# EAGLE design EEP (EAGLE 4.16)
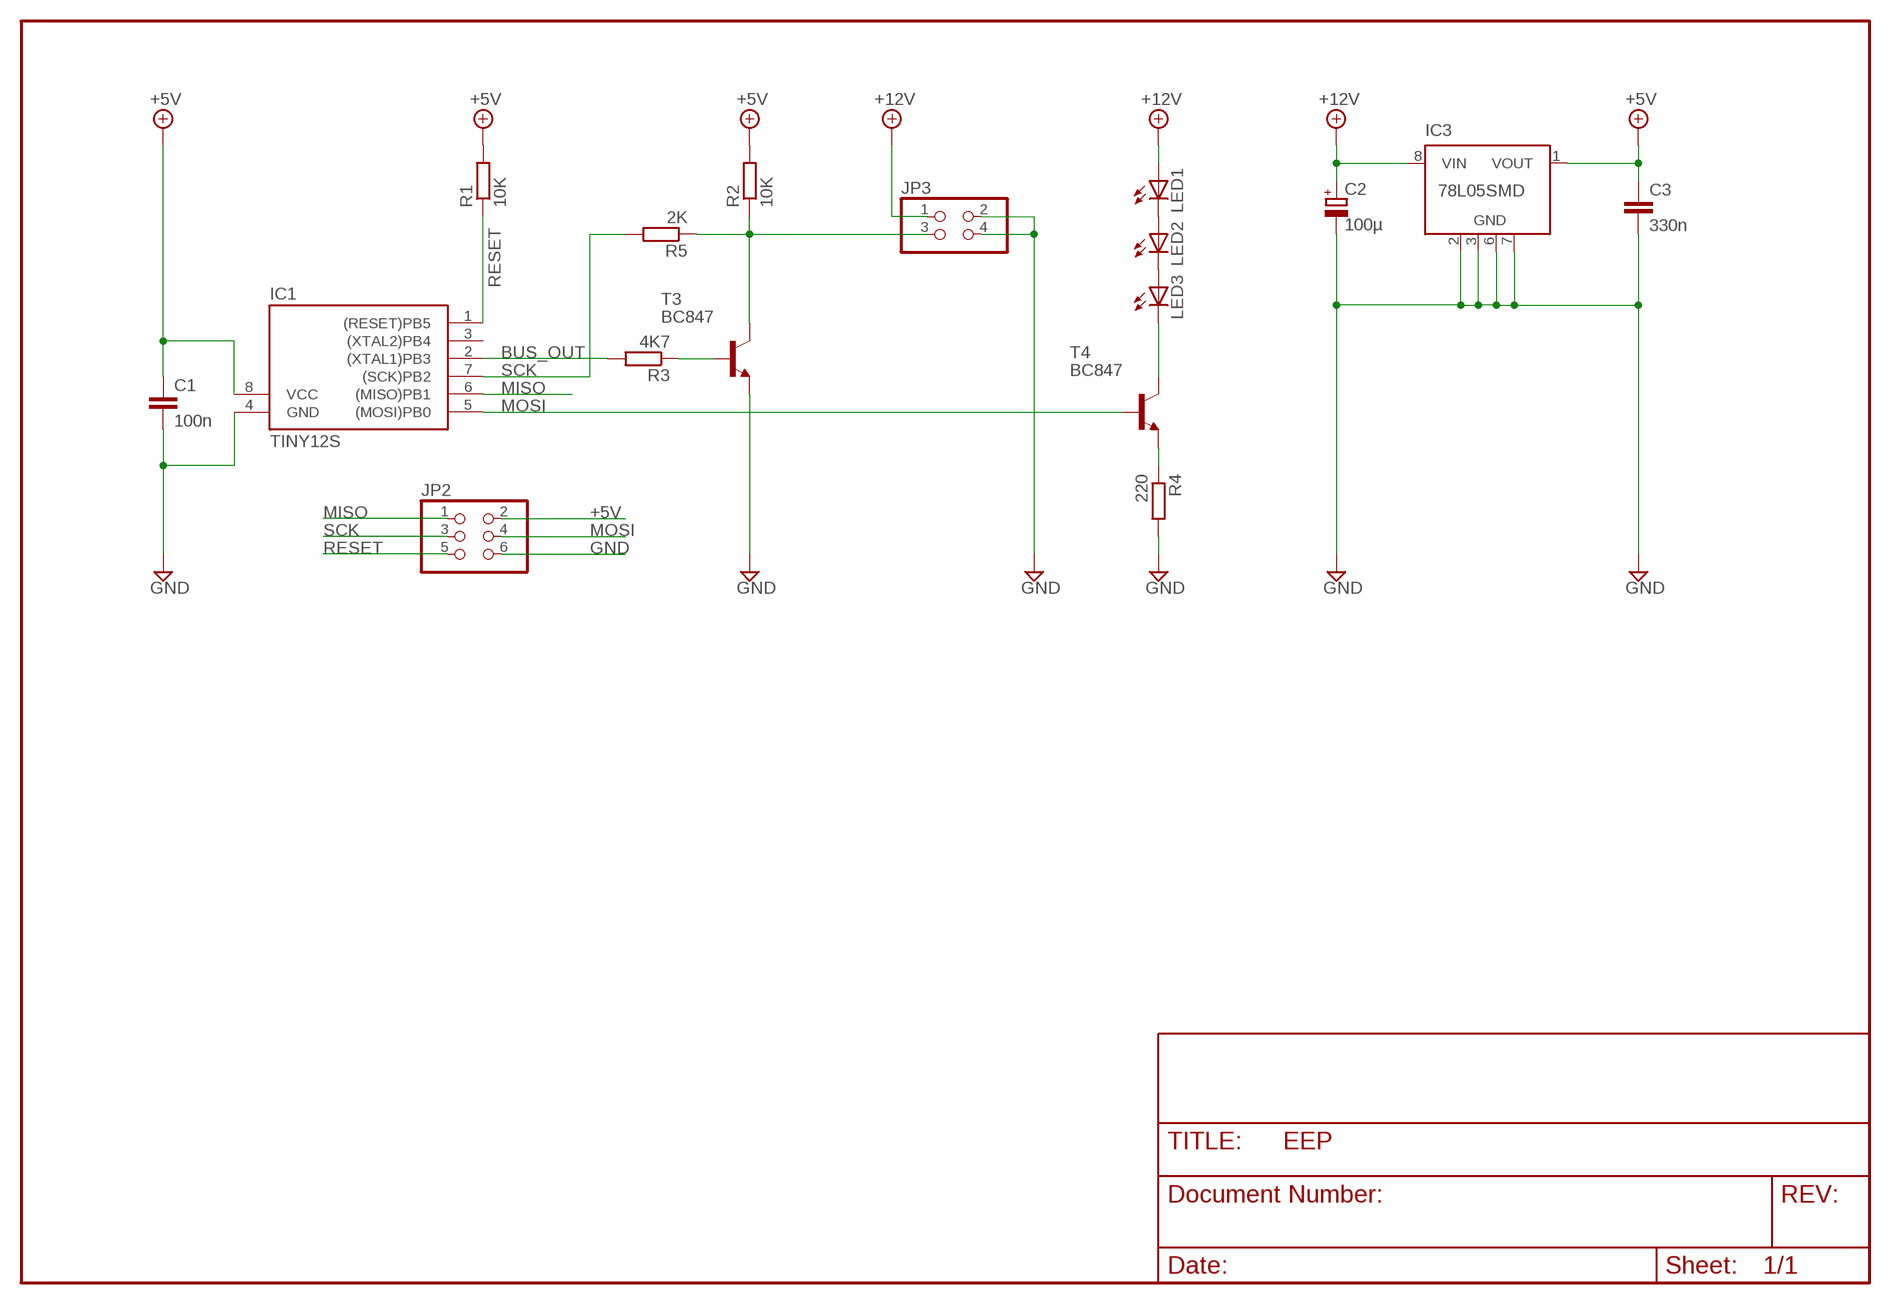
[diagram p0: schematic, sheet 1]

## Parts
C1  100n  C-EUC1206  [C1206]
C2  100µ  CPOL-EU153CLV-0605  [153CLV-0605]
C3  330n  C-EUC1812  [C1812]
IC1  TINY12S  [SOIC8]
IC3  78L05SMD  [SO08]
JP2  PINHD-2X3_2.54-SMD  [2X03SMD]
JP3  PINHD-2X2_2.54-SMD  [2X02SMD]
LED1  LED5MM  [LED5MM]
LED2  LED5MM  [LED5MM]
LED3  LED5MM  [LED5MM]
R1  10K  R-EU_R1206  [R1206]
R2  10K  R-EU_R1206  [R1206]
R3  4K7  R-EU_R1206  [R1206]
R4  220  R-EU_R1206  [R1206]
R5  2K  R-EU_R1206  [R1206]
T3  BC847  [SOT23]
T4  BC847  [SOT23]

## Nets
+5V: C1.1 C3.1 IC1.8(VCC) IC3.1(VOUT) JP2.2 R1.2 R2.2
+12V: C2.+ IC3.8(VIN) JP3.1 LED1.A
BUS_OUT: IC1.2((XTAL1)PB3) R3.2
GND: C1.2 C2.- C3.2 IC1.4(GND) IC3.2(GND) IC3.3(GND) IC3.6(GND) IC3.7(GND) JP2.6 JP3.2 JP3.4 R4.2 T3.2(E)
MISO: IC1.6((MISO)PB1) JP2.1
MOSI: IC1.5((MOSI)PB0) JP2.4 T4.1(B)
N$1: LED3.K(C) T4.3(C)
N$2: R4.1 T4.2(E)
N$3: JP3.3 R2.1 R5.1 T3.3(C)
N$5: R3.1 T3.1(B)
N$6: LED2.K(C) LED3.A
N$7: LED1.K(C) LED2.A
RESET: IC1.1((RESET)PB5) JP2.5 R1.1
SCK: IC1.7((SCK)PB2) JP2.3 R5.2
Unconnected: IC1.3((XTAL2)PB4) IC3.4(NC) IC3.5(NC)

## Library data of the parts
C1 C3 = rcl:C-EU: CAPACITOR, European symbol
C2 = rcl:CPOL-EU: POLARIZED CAPACITOR, European symbol
IC1 = avr-1:TINY12*: MICROCONTROLLER 1 Kbytes FLASH 64 bytes EEPROM
IC3 = linear:78L*SMD: Positive VOLTAGE REGULATOR
JP2 = pinhead-1:PINHD-2X3: PIN HEADER
JP3 = pinhead-1:PINHD-2X2: PIN HEADER
LED1-LED3 = led:LED: LED
R1-R5 = rcl:R-EU_: RESISTOR, European symbol
T3 T4 = transistor:BC847: NPN TRANSISTOR

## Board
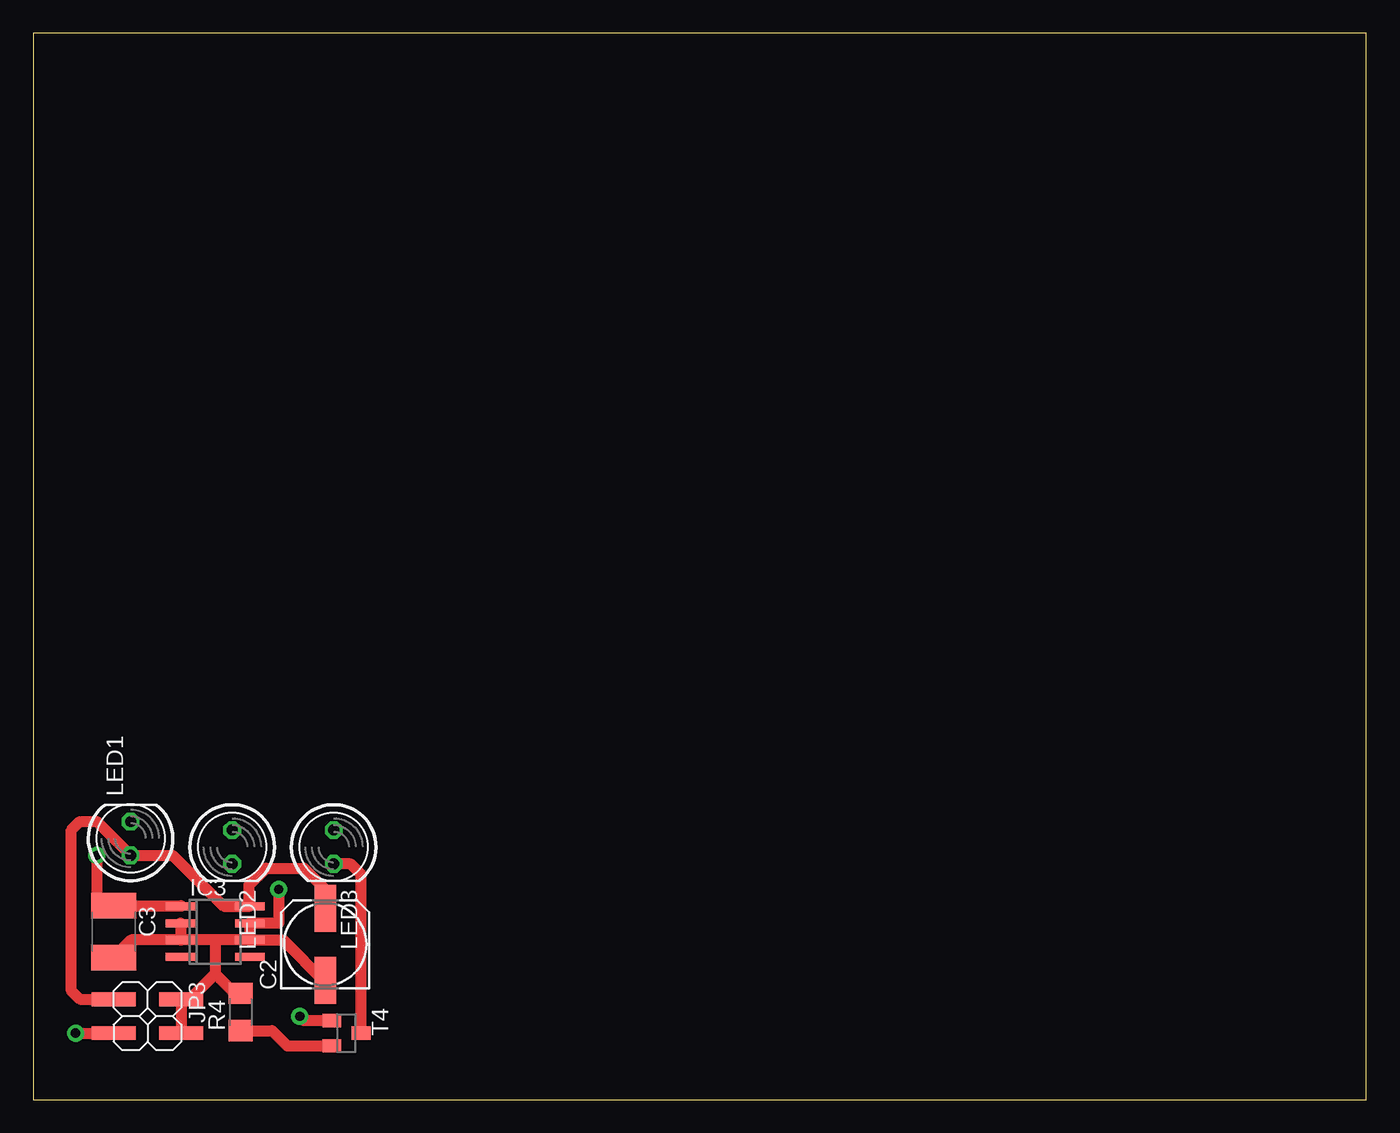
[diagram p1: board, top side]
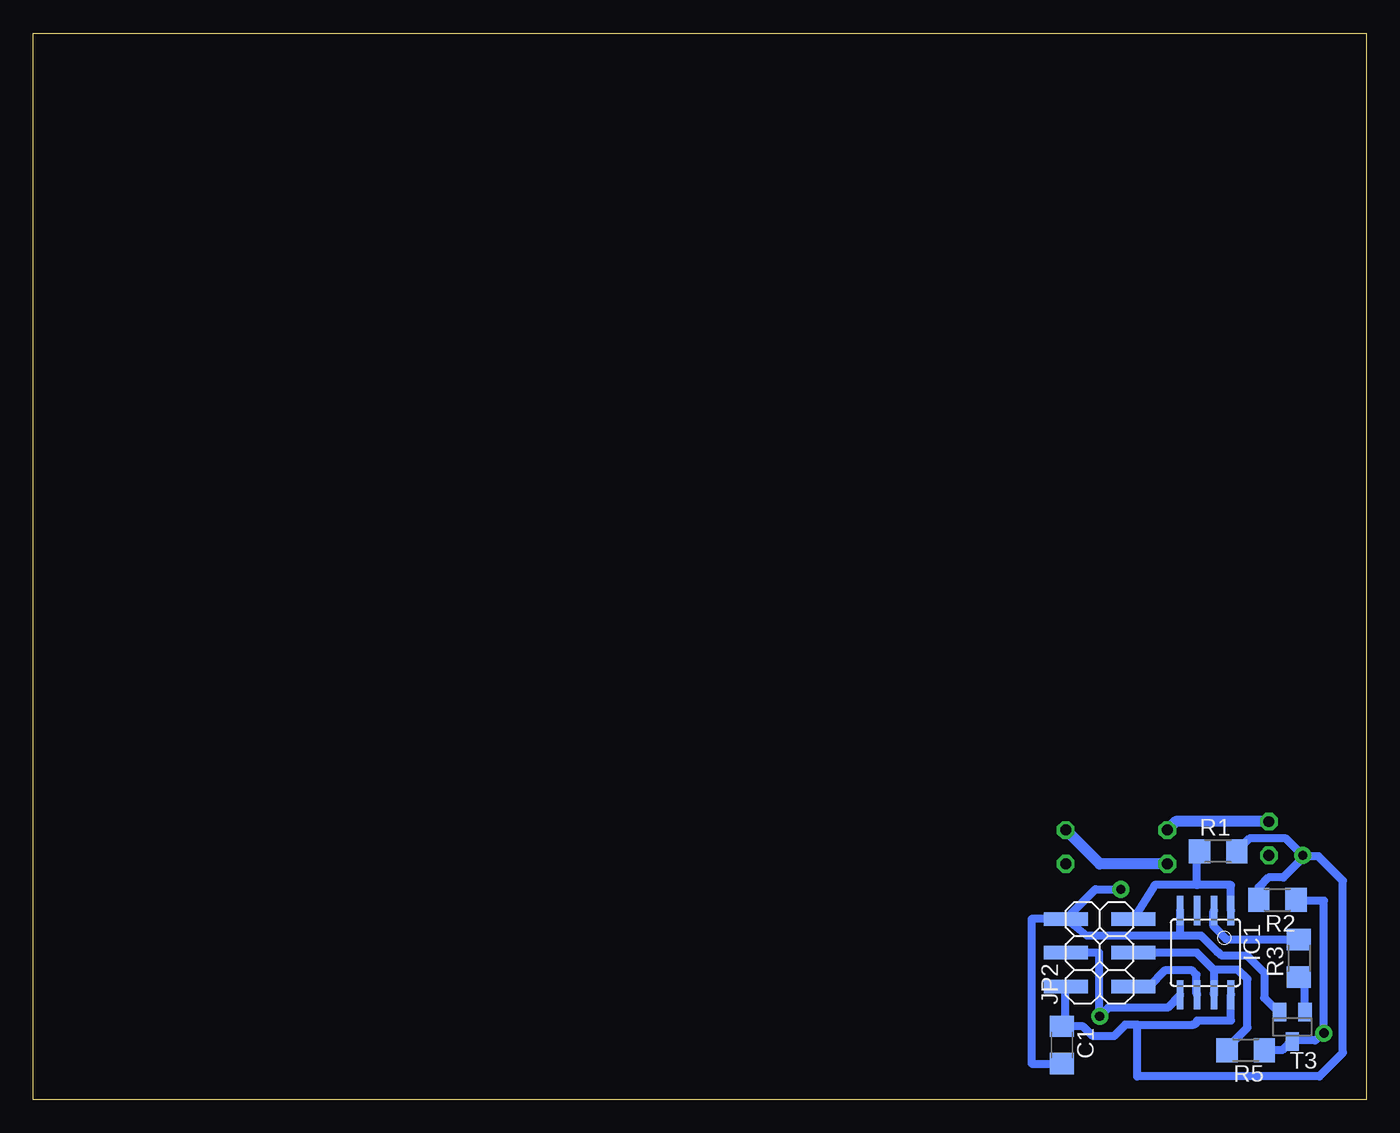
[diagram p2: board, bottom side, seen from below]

Size 100 x 80 mm. Coordinates in mm from the lower left corner, seen from the top.
Outline: 0,0 100,0 100,80 0,80 0,0
Copper layers (1*16): Top 0.035mm / dielectric 1.5mm / Bottom 0.035mm
Design rules "default": minimum track width 10mil, minimum drill 24mil, track to track 8mil, track to pad 8mil, pad to pad 8mil, via to via 8mil, smd to smd 8mil, copper to edge 40mil, drill to drill 8mil, minimum pad ring 10mil, minimum via ring 8mil, stop-mask expansion 4mil, vias tented up to drill 0mil, thermal gap 10mil

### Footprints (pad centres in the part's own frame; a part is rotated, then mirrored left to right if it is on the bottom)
C1206 = smd 1.6 x 1.8: 1 -1.4,0; 2 1.4,0
153CLV-0605 = smd 3.5 x 1.6: + 2.7,0; - -2.7,0
C1812 = smd 1.9 x 3.4: 1 -1.95,0; 2 1.95,0
SOIC8 = smd 0.5 x 2.2: 1 -1.905,-3.154; 2 -0.645,-3.154; 3 0.625,-3.154; 4 1.895,-3.154; 5 1.905,3.154; 6 0.635,3.154; 7 -0.635,3.154; 8 -1.905,3.154
SO08 = smd 0.6 x 2.2: 1 -1.905,-2.6; 2 -0.635,-2.6; 3 0.635,-2.6; 4 1.905,-2.6; 5 1.905,2.6; 6 0.635,2.6; 7 -0.635,2.6; 8 -1.905,2.6
2X03SMD = smd 1.016 x 3.302: 1 -1.27,-3.81; 2 -1.27,1.27; 3 1.27,-3.81; 4 1.27,1.27; 5 3.81,-3.81; 6 3.81,1.27
2X02SMD = smd 1.016 x 3.302: 1 -1.27,-3.81; 2 -1.27,1.27; 3 1.27,-3.81; 4 1.27,1.27
LED5MM = drill 0.813 octagon: A -1.27,0; K 1.27,0
R1206 = smd 1.6 x 1.8: 1 -1.4,0; 2 1.4,0
SOT23 = smd 1 x 1.4: 1 -0.95,-1.1; 2 0.95,-1.1; 3 0,1.1

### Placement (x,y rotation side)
C1  22.82,4.09 270 bottom
C2  21.9,11.65 90 top
C3  6.03,12.6 270 top
IC1  12.06,11.01 180 bottom
IC3  13.65,12.6 270 top
JP2  21.27,9.74 90 bottom
JP3  9.84,6.25 270 top
LED1  7.3,19.58 90 top
LED2  14.92,18.95 270 top
LED3  22.54,18.95 270 top
R1  11.11,18.63 0 bottom
R2  6.66,14.98 180 bottom
R3  5.04,10.6 90 bottom
R4  15.55,6.57 90 top
R5  9.04,3.71 180 bottom
T3  5.55,5.46 180 bottom
T4  23.49,4.98 270 top

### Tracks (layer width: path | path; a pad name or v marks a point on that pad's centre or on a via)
+5V  (via drill 0.7 pad 1.27)
  Top 0.813: 11.11,14.5 IC3.1 | 11.11,14.5 11.06,14.55 C3.1 6.03,14.5 4.76,14.5 v4.76,18.32 | 11.11,14.5 10.47,14.5
  Bottom 0.61: v4.76,18.32 6.03,19.59 8.75,19.59 R1.2 | 17.17,5.62 13.01,5.62 arc-90 12.69,5.93 11.42,5.93 | 17.17,5.62 18.09,5.62 18.09,5.58 18.92,4.76 20.5,4.76 21.24,5.49 22.57,5.49 | IC1.8 10.15,5.93 11.42,5.93 | 11.42,5.93 10.47,5.93 | 22.41,8.41 22.47,8.41 JP2.2 22.57,8.47 | 3.49,1.81 3.49,1.74 3.52,1.74 | v4.76,18.32 4.79,18.28 4.79,18.25 4.63,18.25 | 4.63,18.25 3.58,18.25 1.74,16.41 1.74,3.52 3.52,1.74 | 3.52,1.74 17.17,1.74 17.17,5.62 | 22.57,8.47 22.57,8.57 | 22.57,5.49 C1.1 | 22.57,5.49 22.57,8.47 | R2.2 8.06,15.93 7.33,16.66 6.22,16.66 4.63,18.25 | 4.63,18.25 4.69,18.32 v4.76,18.32
+12V
  Top 0.813: 16.19,14.5 14.28,14.5 10.47,18.32 LED1.A 4.76,20.86 3.49,20.86 2.85,20.22 2.85,8.15 3.49,7.52 JP3.1 | C2.+ 21.9,15.77 20.31,17.36 17.46,17.36 16.19,16.09 16.19,14.5 | 16.19,14.5 IC3.8
BUS_OUT
  Bottom 0.61: IC1.2 11.46,14.12 11.46,13.01 10.44,12 R3.2 | IC1.2
GND  (via drill 0.7 pad 1.27)
  Top 0.813: C3.2 7.34,11.96 IC3.3 11.11,11.96 | IC3.2 11.11,13.17 11.11,11.96 | 16.19,11.96 11.11,11.96 | 16.19,11.96 16.25,12.02 IC3.7 18.41,13.23 v18.41,15.77 | 16.19,11.96 13.65,11.96 13.65,9.42 | 16.19,11.96 IC3.6 18.73,11.96 21.9,8.79 C2.- | 13.65,9.42 11.74,7.52 JP3.2 JP3.4 | R4.2 15.1,7.97 13.65,9.42
  Bottom 0.61: 12.38,12.28 12.69,12.28 | JP2.6 20.31,15.77 v18.41,15.77 | 12.38,12.28 14,12.28 | 14,12.28 20.95,12.28 JP2.6 | 11.17,11.08 11.11,11.01 | 11.17,11.08 12.38,12.28 | JP2.6 25.11,13.55 25.11,3.33 | 14,12.28 14,12.38 13.95,12.42 IC1.4 | 25.11,3.33 25.11,3.01 | C1.2 25.11,2.69 25.11,3.33 | 11.17,11.08 11.14,11.11 10.82,10.79 8.92,10.79 7.65,9.52 7.65,7.62 6.53,6.5 6.5,6.54 T3.2
MISO
  Bottom 0.61: JP2.1 16.31,8.47 15.11,9.68 13.04,9.68 12.73,9.36 12.73,7.93 12.69,7.9 IC1.6
MOSI  (via drill 0.7 pad 1.27)
  Top 0.813: T4.1 20.31,5.93 v20,6.25
  Bottom 0.61: v20,6.25 19.68,6.57 | v20,6.25 19.36,6.88 14.88,6.88 13.96,7.81 IC1.5 | 20.03,6.25 19.87,6.19 | v20,6.25 20.03,6.25 | JP2.4 20.03,11.01 20.03,6.25
N$1
  Top 0.813: T4.3 24.59,16.9 23.81,17.68 LED3.K
N$2
  Top 0.813: R4.1 17.9,5.17 19.04,4.03 22.22,4.03 T4.2
N$3  (via drill 0.7 pad 1.27)
  Top 0.813: v3.17,4.98 JP3.3
  Bottom 0.61: v3.17,4.98 2.85,4.98 | v3.17,4.98 3.17,4.66 | v3.17,4.98 3.17,4.95 | 3.2,5.08 3.2,5.01 v3.17,4.98 | v3.17,4.98 3.17,14.92 5.26,14.92 R2.1 | 5.58,4.44 5.55,4.41 T3.3 | R5.1 6.31,3.71 5.58,4.44 | 3.2,5.08 3.17,5.04 v3.17,4.98 | 5.58,4.44 3.84,4.44 3.2,5.08
N$5
  Bottom 0.61: 5.11,9.2 5.1,9.2 | 5.1,9.2 R3.1 | T3.1 4.6,8.7 5.1,9.2
N$6
  Bottom 0.813: LED2.K 20,17.68 LED3.A
N$7
  Bottom 0.813: LED1.K 14.28,20.86 LED2.A
RESET
  Bottom 0.61: IC1.1 10.15,16.09 12.69,16.09 | 12.69,16.09 15.87,16.09 JP2.5 | R1.1 12.69,18.45 12.69,16.09
SCK
  Bottom 0.61: 11.42,9.74 12.69,11.01 JP2.3 | 11.42,9.74 9.61,9.74 8.92,9.04 8.92,5.39 9.97,4.34 9.97,3.71 | 9.97,3.71 10.03,3.65 | 9.97,3.71 R5.2 | IC1.7 11.42,7.9 11.46,7.93 11.42,7.96 11.42,9.74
